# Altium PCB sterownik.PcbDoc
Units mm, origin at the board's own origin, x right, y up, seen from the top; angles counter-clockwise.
Board outline 218.44 x 160.02 mm, 2 copper layers (Top Layer, Bottom Layer); 44 components, 46 nets, 196 pads, 52 vias.
Unrouted connection lines stored in the file: 1.
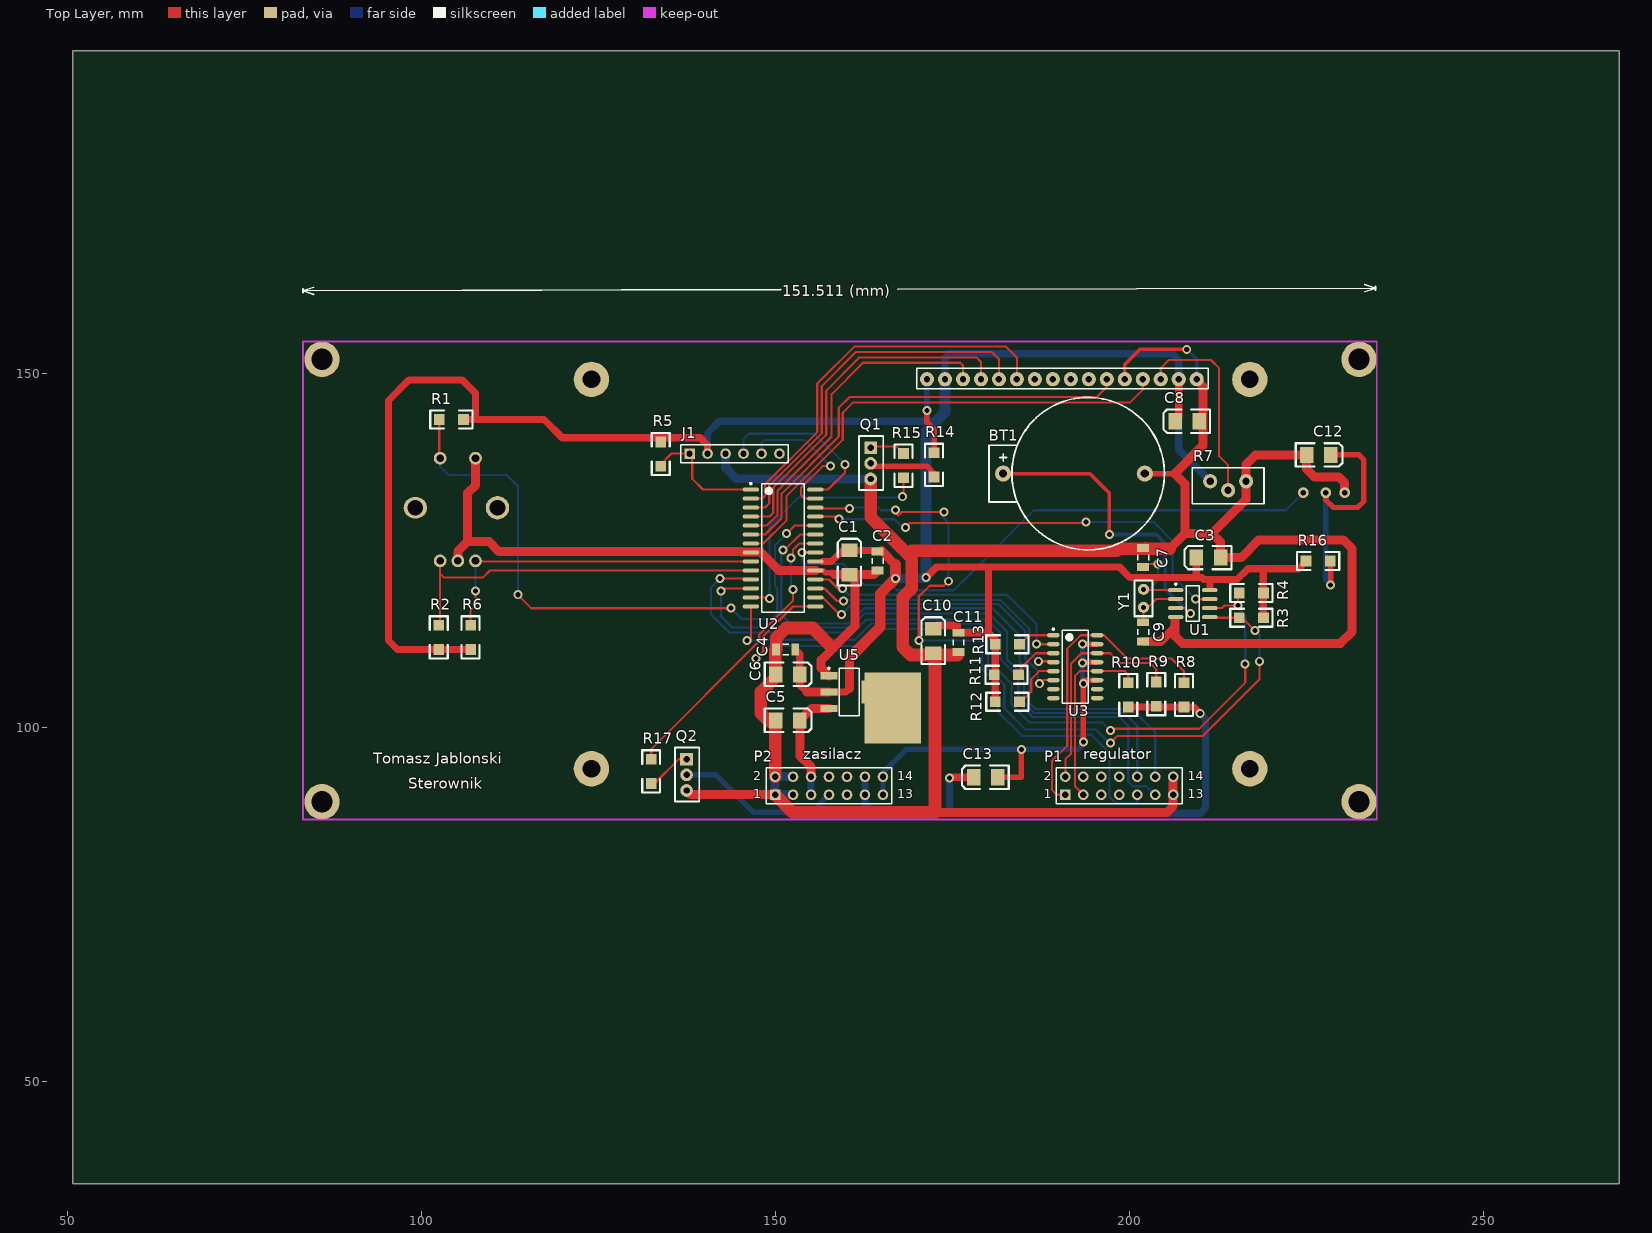
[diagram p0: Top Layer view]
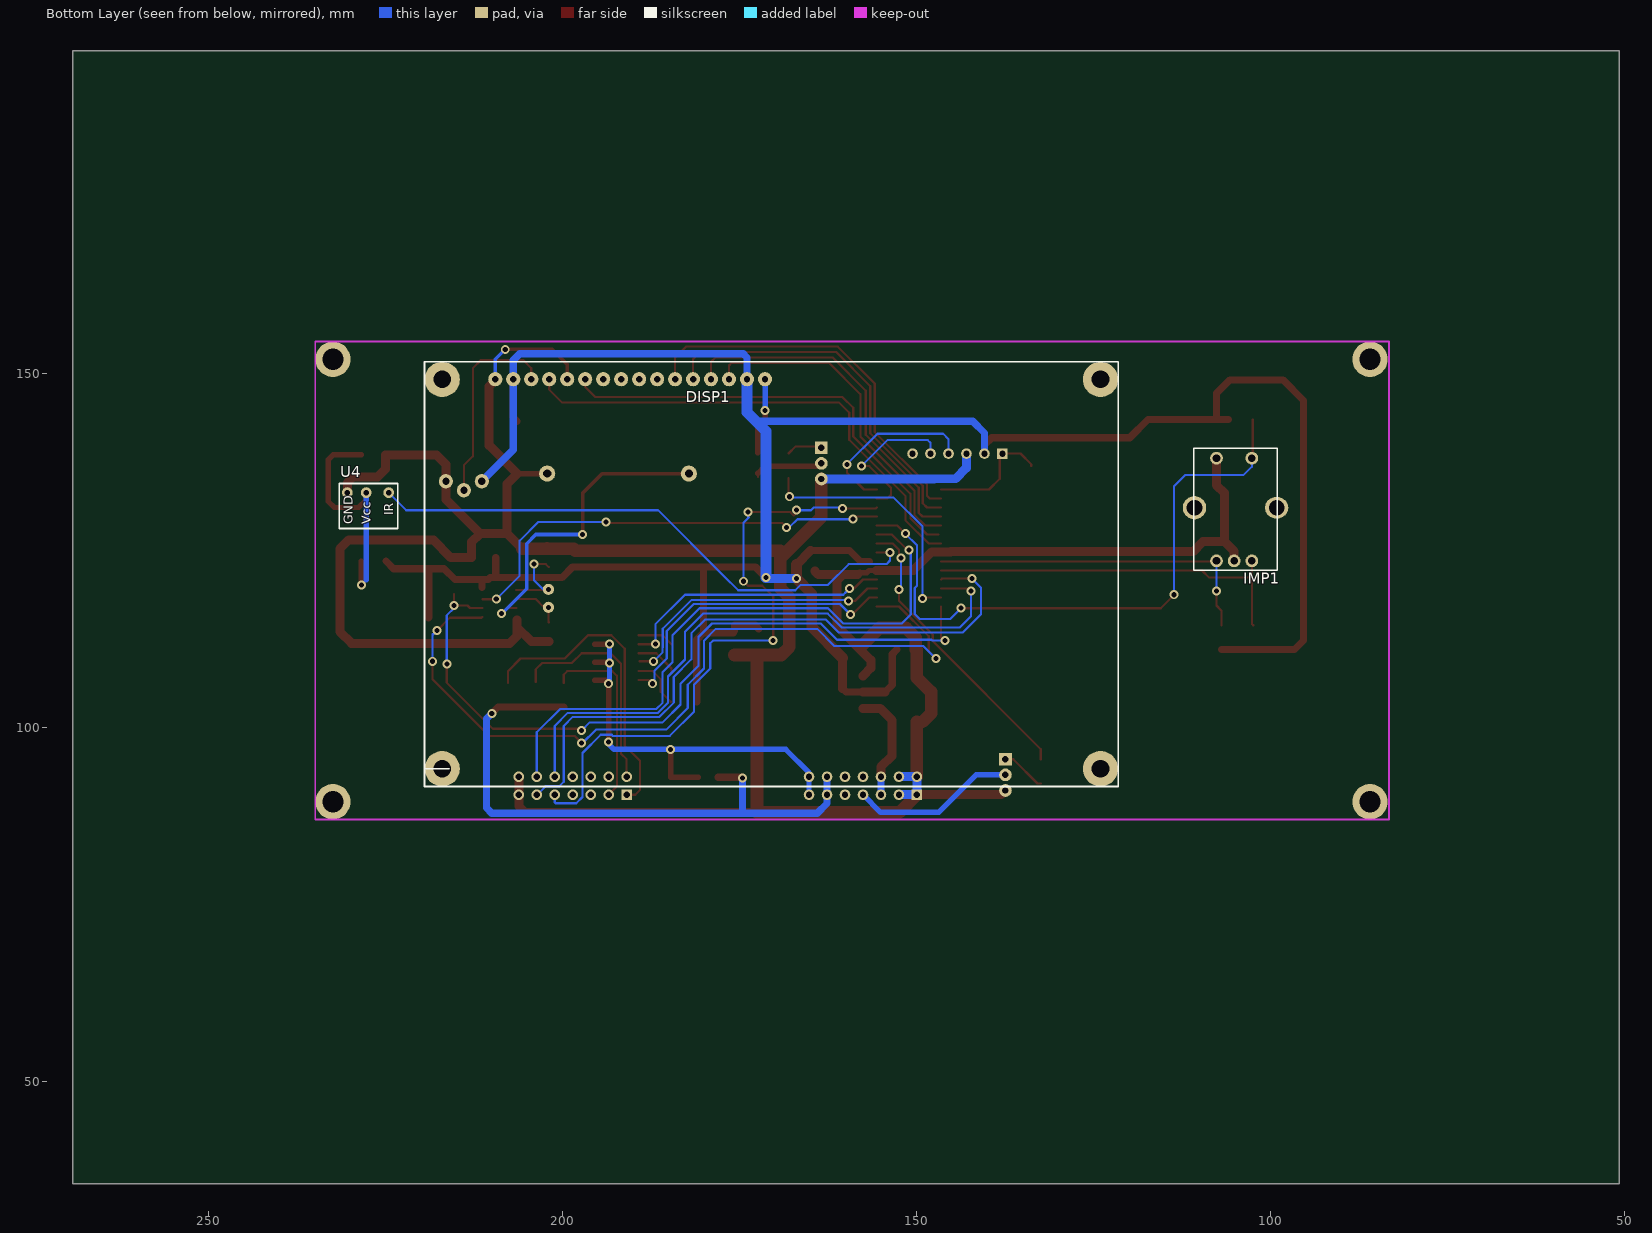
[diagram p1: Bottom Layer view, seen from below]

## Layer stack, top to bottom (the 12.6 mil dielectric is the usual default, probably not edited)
Top Solder: solder mask 0.0102, Solder Resist, Dk 3.5
Top Layer: signal copper 0.0356
Dielectric 1: dielectric 0.32, FR-4, Dk 4.8
Bottom Layer: signal copper 0.0356
Bottom Solder: solder mask 0.0102, Solder Resist, Dk 3.5

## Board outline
50.8,35.56 50.8,195.58 269.24,195.58 269.24,35.56

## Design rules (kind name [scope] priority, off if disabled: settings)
Clearance [All] p1: gap=0.254
PolygonConnect [All] p1: connectstyle=Relief reliefconductorwidth=0.254 reliefentries=4 polygonreliefangle="90 Angle" airgapwidth=0.254
RoomDefinition sterownik [InComponentClass('sterownik')] p1: confinementstyle=ConfineIn formatcopy=TRUE lockcomponents=FALSE outline 0,0 50.8,0 50.8,25.4 0,25.4
RoutingVias [All] p1: holewidth=0.711 width=1.27 viastyle="Through Hole" minholewidth=0.711 minwidth=1.27 maxholewidth=0.711 maxwidth=1.27
SolderMaskExpansion [All] p1: expansion=0.102
Width GNDI [InNet('GNDI')] p1: maxlimit=0.762 minlimit=0.762 preferedwidth=0.762
Width +VDD [InNet('+VDD')] p2: maxlimit=1.016 minlimit=1.016 preferedwidth=1.016
Width +5VI [InNet('+5VI')] p3: maxlimit=1.016 minlimit=1.016 preferedwidth=1.016
Width GND [InNet('GND')] p4: maxlimit=1.27 minlimit=1.27 preferedwidth=1.27
Width +5V [InNet('+5V')] p5: maxlimit=1.27 minlimit=1.016 preferedwidth=1.27
Width [All] p6: maxlimit=0.305 minlimit=0.305 preferedwidth=0.305
30 further rules are at their usual default settings.

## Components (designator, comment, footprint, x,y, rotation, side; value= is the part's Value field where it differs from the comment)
BT1 "Battery" BAT 194,135.5 r180 top
C1 "" 3528 160.5,125 r90 top
C2 "Cap" C1206 164.5,123.5 r270 top
C3 "" 3528 209.5,124 r180 top
C4 "Cap" C1206 151.5,111 r0 top
C5 "ELECTRO2" 3528 153.5,101 r0 top
C6 "ELECTRO2" 3528 153.5,107.5 r0 top
C7 "Cap" C1206 202,124 r90 top
C8 "" 3528 206.502,143.256 r180 top
C9 "Cap" C1206 202,113.5 r270 top
C10 "" 3528 172.339,113.919 r90 top
C11 "Cap" C1206 175.895,112.014 r270 top
C12 "" 3528 228.5,138.5 r0 top
C13 "" 3528 178.054,92.964 r180 top
DISP1 "LCD" LCD4x20 170.561,121.666 r180 bottom locked
IMP1 "IMP_PIHER" IMP_PIHER 105.492,130.732 r180 bottom
J1 "ICSP" HDR1X6 137.922,138.684 r0 top
P1 "regulator" HDR2X7 191,90.5 r0 top
P2 "zasilacz" HDR2X7 150,90.5 r0 top
Q1 "" BD139 163.5,139.5 r0 top
Q2 "BD139" BD139 137.5,95.5 r0 top
R1 "" 1206 106,143.5 r180 top
R2 "" 1206 102.5,111 r90 top
R3 "" 1206 219,115.5 r180 top
R4 "" 1206 219,119 r180 top
R5 "" 1206 133.858,136.906 r90 top
R6 "" 1206 107,111 r90 top
R7 "RPot" PR 214,133.5 r0 top
R8 "" 1206 207.772,102.87 r90 top
R9 "" 1206 203.835,102.997 r90 top
R10 "" 1206 199.898,102.87 r90 top
R11 "" 1206 181.102,103.632 r0 top
R12 "" 1206 180.975,107.442 r0 top
R13 "" 1206 181.102,111.76 r0 top
R14 "" 1206 172.466,138.811 r270 top
R15 "" 1206 168.148,135.255 r90 top
R16 "" 1206 225,123.5 r0 top
R17 "" 1206 132.5,95.5 r270 top
U1 "DS1307Z" SOIC8N_N 209,117.5 r0 top
U2 "PIC16F1936-I/SO" SOIC-SO28_N 151.13,125.349 r0 top
U3 "TLP281-4" TLP281-4 192.405,108.585 r0 top
U4 "IR" IR 228,131 r180 bottom
U5 "SPX1117" SOT223_N 160.5,105 r0 top
Y1 "XTAL" RAD0.1 202.057,116.967 r90 top

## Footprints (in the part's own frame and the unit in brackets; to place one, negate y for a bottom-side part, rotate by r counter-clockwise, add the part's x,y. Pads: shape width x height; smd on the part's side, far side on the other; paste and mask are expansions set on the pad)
1206 [mil]
  rect 60x60 smd: 1(0,0) 2(135,0)
  silkscreen extent -50,-50 185,50
3528 [mil]
  rect 75x90 smd: 1(0,0) 2(-135,0)
  silkscreen extent -195,-65 65,65
BAT [mil]
  round 90 hole 45: 1(463.58,-13.78) 2(-323.82,-13.78)
  silkscreen extent -433,-438 542,410
BD139 [mm]
  rect 1.8x1.8 hole 0.9: 1(0,0)
  round 1.8 hole 0.9: 2(0,-2.2) 3(0,-4.4)
  silkscreen extent -1.65,-5.97 1.78,1.65
C1206 [mm] "Chip Capacitor, Body 3.2x1.6mm, IPC High Density"
  rect 1.1x1.7 smd: 1(-1.35,0) 2(1.35,0)
  silkscreen extent -0.4,-0.75 0.4,0.75, body extent -1.7,-0.9 1.7,0.9, height 1.3
HDR1X6 [mm] "Connector; Header; 6 Position"
  rect 1.5x1.5 hole 0.9: 1(0,0)
  round 1.5 hole 0.9: 2(2.54,0) 3(5.08,0) 4(7.62,0) 5(10.16,0) 6(12.7,0)
  silkscreen extent -1.27,-1.27 13.97,1.27
HDR2X7 [mm] "Connector; Header; 7x2 Position"
  rect 1.5x1.5 hole 0.9: 1(0,0)
  round 1.5 hole 0.9: 2(0,2.54) 3(2.54,0) 4(2.54,2.54) 5(5.08,0) 6(5.08,2.54) 7(7.62,0) 8(7.62,2.54) 9(10.16,0) 10(10.16,2.54) 11(12.7,0) 12(12.7,2.54) 13(15.24,0) 14(15.24,2.54)
  silkscreen extent -1.27,-1.27 16.51,3.81
IMP_PIHER [mm]
  round 1.8 hole 1.1: 1(-2.2,-7.2) 2(0.3,-7.2) 3(2.8,-7.2) 4(-2.2,7.3) 5(2.8,7.3)
  round 3.3 hole 2.2: 71(-5.3,0.3)
  oval 3.3x3 hole 2.2: 72(6.3,0.3)
  silkscreen extent -5.4,-8.5 6.4,8.7
IR [mil]
  round 60 hole 30: 1(-96.73,85.43) 2(8.27,85.43) 3(133.27,85.43)
  silkscreen extent -142,-115 183,135
LCD4x20 [mm]
  round 5 hole 2.5: 0(-46.5,-27.5) 0(-46.5,27.5) 0(46.5,-27.5) 0(46.5,27.5)
  round 2 hole 0.9: 1(-39,27.525) 2(-36.46,27.525) 3(-33.92,27.525) 4(-31.38,27.525) 5(-28.84,27.525) 6(-26.3,27.525) 7(-23.76,27.525) 8(-21.22,27.525) 9(-18.68,27.525) 10(-16.14,27.525) 11(-13.6,27.525) 12(-11.06,27.525) 13(-8.52,27.525) 14(-5.98,27.525) 15(-3.44,27.525) 16(-0.9,27.525)
  silkscreen extent -49,-30 49,30
PR [mil]
  round 79 hole 40: 1(-100,50) 2(100,50) 3(0,0)
  silkscreen extent -200,-75 200,125
RAD0.1 [mil]
  round 62 hole 28: 1(0,0) 2(100,0)
  silkscreen extent -50,-50 150,50
SOIC8N_N [mm] "SOIC, 8-Leads, Body 4.9x3.9mm, Pitch 1.27mm, IPC Medium Density"
  oval 2.2x0.6 smd: 1(-2.4,1.905) 2(-2.4,0.635) 3(-2.4,-0.635) 4(-2.4,-1.905) 5(2.4,-1.905) 6(2.4,-0.635) 7(2.4,0.635) 8(2.4,1.905)
  silkscreen extent -2.52,-2.5 0.9,2.88, body extent -2,-2.5 2,2.5, height 1.75
SOIC-SO28_N [mm] "SOIC, 28-Leads, Body 17.9x7.5mm, Pitch 1.27mm, IPC Medium Density"
  oval 2.3x0.6 smd: 1(-4.55,8.255) 2(-4.55,6.985) 3(-4.55,5.715) 4(-4.55,4.445) 5(-4.55,3.175) 6(-4.55,1.905) 7(-4.55,0.635) 8(-4.55,-0.635) 9(-4.55,-1.905) 10(-4.55,-3.175) 11(-4.55,-4.445) 12(-4.55,-5.715) 13(-4.55,-6.985) 14(-4.55,-8.255) 15(4.55,-8.255) 16(4.55,-6.985) 17(4.55,-5.715) 18(4.55,-4.445) 19(4.55,-3.175) 20(4.55,-1.905) 21(4.55,-0.635) 22(4.55,0.635) 23(4.55,1.905) 24(4.55,3.175) 25(4.55,4.445) 26(4.55,5.715) 27(4.55,6.985) 28(4.55,8.255)
  silkscreen extent -4.67,-9.05 3,9.23, body extent -3.8,-9.05 3.8,9.05, height 2.65
SOT223_N [mm] "SOT223, 4-Leads, Body 6.5x3.5mm, Pitch 2.3mm, Lead Span 7mm, IPC Medium Density"
  rect 2.4x1 smd: 1(-2.9,2.3) 2(-2.9,0) 3(-2.9,-2.3)
  rect 2.4x3.3 smd: 4(2.9,0)
  silkscreen extent -3.02,-3.35 1.4,3.47, body extent -1.85,-3.35 1.85,3.35, height 1.7
TLP281-4 [mm]
  oval 1.75x0.6 smd: 1(-3.1,4.445) 2(-3.1,3.175) 3(-3.1,1.905) 4(-3.1,0.635) 5(-3.1,-0.635) 6(-3.1,-1.905) 7(-3.1,-3.175) 8(-3.1,-4.445) 9(3.1,-4.445) 10(3.1,-3.175) 11(3.1,-1.905) 12(3.1,-0.635) 13(3.1,0.635) 14(3.1,1.905) 15(3.1,3.175) 16(3.1,4.445)
  silkscreen extent -3.22,-5.15 1.83,5.42, body extent -2.2,-5.15 2.2,5.15, height 2

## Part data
BT1: "Multicell Battery"
C1 C3 C8 C10 C12 C13: library part ELECTRO2, "Electrolytic Capacitor"
C2 C4 C7 C9 C11: "Capacitor"
C5 C6: "Electrolytic Capacitor"
J1: library part "Header 6", "Header, 6-Pin"
P1 P2: library part "Header 7X2", "Header, 7-Pin, Dual row"
Q1 Q2: library part NPN1, "NPN Transistor"
R1 R2 R3 R4 R5 R6 R8 R9 R10 R11 R12 R13 R14 R15 R16 R17: library part Res2, "Resistor"
R7: "Potentiometer"
U1: "64 X 8 Serial Real-Time Clock"
U2: "CMOS Microcontroller with LCD Driver, 8K (words) Program Memory, 256 Bytes Data Memory, 512 Bytes SRAM, 25 I/O's, 1.8V-5.5V, 28-Pin SOIC, Industrial Temperature"
Y1: "Crystal Oscillator"

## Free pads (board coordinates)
  round 5 hole 3: 0(86,89.5) 0(86,152) 0(232.5,89.5) 0(232.5,152)
  rect 8x10 smd: 0(166.624,102.743)

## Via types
v1: diameter 1.27, hole 0.711, Top Layer to Bottom Layer, 52 vias

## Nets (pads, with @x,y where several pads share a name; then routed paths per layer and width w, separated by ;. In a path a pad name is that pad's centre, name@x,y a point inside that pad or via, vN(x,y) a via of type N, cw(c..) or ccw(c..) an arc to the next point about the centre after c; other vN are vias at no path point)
+5V: C1.1 C2.1 C3.1 C4.2 C6.1 C8.1 C10.1 C11.1 DISP1.2 DISP1.15 J1.2 pad.0@166.624,102.743 R1.1 R2.1 R3.1 R4.1 R5.2 R6.1 R7.1 R11.1 R12.1 R13.1 R16.1 U1.8 U2.20 U5.2 | length 372
  Top Layer w1.016: R1.1 117.358,143.5 119.937,140.921 139.446,140.921 140.462,139.905 J1.2 ; R6.1 R2.1 96.649,111 95.377,112.272 95.377,146.177 98.298,149.098 105.791,149.098 107.696,147.193 107.696,143.627 ; C4.2 153.5,110.35 C6.1 153.5,106 154.5,105 ; U2.20@156.718,123.444 157.988,123.444 159.544,125 C1.1 C2.1@165,125 ; U5.2 160,105 160.5,105.5 ; v1(171.323,121.158) 172.847,122.682 180.213,122.682 ; C10.1 172.847,114.427 175.768,114.427 C11.1@175.768,113.665 ; C11.1 180.133,113.364 ; R11.1 R13.1 181.102,112.395 180.133,113.364 ; C8.1 207.021,143.775 DISP1.2 ; 209.5,121.412 C3.1 ; 211.455,119.761 211.455,120.904 ; R3.1 218.948,115.552 218.948,122.428 ; R16.1 223.928,122.428 218.948,122.428 ; 180.133,113.364 180.133,122.602 180.213,122.682 ; 180.213,122.682 198.628,122.682 200.152,121.158 210.312,121.158 210.566,120.904 211.455,120.904 ; 211.455,120.904 215.265,120.904 216.789,122.428 218.948,122.428
  Top Layer w1.27: 154.5,105 U5.2 ; 160.5,105.5 160.5,109.827 ; C2.1@165,125 167,123
  Top Layer w1.524: 160.5,109.827 164.846,114.173 164.846,118.877 v1(167,121.031) 167,123
  Bottom Layer w1.016: J1.2 140.462,141.605 142.113,143.256 172.662,143.256 ; DISP1.15 174.001,152.262 174.52,152.781 206.121,152.781 207.021,151.881 DISP1.2 207.021,139.209 R7.1
  Bottom Layer w1.27: v1(167,121.031) 171.196,121.031 v1(171.323,121.158)
  Bottom Layer w1.524: v1(171.323,121.158) 171.323,141.848 174.001,144.526 DISP1.15
+5VI: C13.1 P2.11 P2.12 R8.1 R9.1 R10.1 | length 85.5
  Top Layer w1.016: v1(174.625,92.837) 174.752,92.964 C13.1 ; R10.1 R8.1 209.169,102.87 v1(210.058,101.981)
  Bottom Layer w1.016: P2.12 P2.11 162.7,89.268 164.079,87.889 174.371,87.889 ; v1(174.625,92.837) 174.625,88.143 174.371,87.889 ; v1(210.058,101.981) 210.82,101.219 210.82,88.646 210.063,87.889 174.371,87.889
+VDD: C5.1 P2.5 P2.6 U5.3 | length 16
  Top Layer w1.27: P2.6 155.08,94.42 153.5,96 C5.1 155.2,102.7 U5.3
  Bottom Layer w1.016: P2.5 P2.6
A: IMP1.1 R6.2 U2.9 | length 48.3
  Top Layer w0.305: R6.2 107,116.525 107.696,117.221 v1(107.696,119.253) ; IMP1.1 107.78,123.444 U2.9
  Bottom Layer w0.305: IMP1.1 107.692,119.257 v1(107.696,119.253)
B: IMP1.3 R2.2 U2.10 | length 53.7
  Top Layer w0.305: R2.2 102.692,114.621 102.692,121.717 ; IMP1.3 102.692,121.717 ; U2.10 109.728,122.174 108.712,121.158 103.251,121.158 102.692,121.717
BAT: BT1.1 U1.3 | length 44.2
  Top Layer w0.305: U1.3 207.874,116.865 v1(208.661,116.078)
  Top Layer w0.508: BT1.1 194.477,135.85 197.231,133.096 v1(197.231,127.254)
  Bottom Layer w0.508: v1(197.231,127.254) 203.835,127.254 205.13,125.959 205.13,119.609 v1(208.661,116.078)
BLIGHT: R15.1 U2.13 | length 36.1
  Top Layer w0.305: U2.13 v1@149.225,118.364 ; v1(168.021,132.588) 168.148,132.715 R15.1
  Bottom Layer w0.305: v1(149.225,118.237) 149.225,128.397 153.289,132.461 167.894,132.461 v1(168.021,132.588)
CS: U2.16 U3.6 | length 43.3
  Top Layer w0.305: U2.16 156.718,118.364 159.131,115.951 v1(159.385,115.951) ; v1(187.325,106.172) 187.833,106.68 U3.6
  Bottom Layer w0.305: v1(159.385,115.951) 160.858,117.424 181.534,117.424 185.344,113.614 185.344,109.728 187.071,108.001 187.071,106.426 v1(187.325,106.172)
CSI: P1.3 R10.2 U3.12 | length 26.4
  Top Layer w0.305: P1.3 192.384,91.656 192.384,107.294 193.04,107.95 U3.12 199.39,107.95 199.898,107.442 R10.2
D0: DISP1.11 U2.2 | length 55.2
  Top Layer w0.305: U2.2 148.209,132.334 148.59,132.715 148.59,134.344 155.956,141.71 155.956,148.59 161.163,153.797 182.626,153.797 184.161,152.262 DISP1.11
D1: DISP1.12 U2.3 | length 52.7
  Top Layer w0.305: U2.3 148.59,131.064 149.174,131.648 149.174,134.138 156.591,141.555 156.591,148.209 161.417,153.035 180.594,153.035 181.621,152.008 DISP1.12
D2: DISP1.13 U2.4 | length 50.2
  Top Layer w0.305: U2.4 149.225,129.794 149.733,130.302 149.733,133.858 157.226,141.351 157.226,147.574 161.925,152.273 178.435,152.273 179.081,151.627 DISP1.13
D3: DISP1.14 U2.5 | length 47.1
  Top Layer w0.305: U2.5 148.844,128.524 150.368,130.048 150.368,133.477 157.988,141.097 157.988,147.066 162.433,151.511 176.149,151.511 176.541,151.119 DISP1.14
E: DISP1.6 U2.6 | length 64
  Top Layer w0.305: U2.6@146.939,127.254 148.59,127.254 150.927,129.591 150.927,133.02 159.004,141.097 159.004,145.161 160.528,146.685 195.453,146.685 196.861,148.093 DISP1.6
GND: BT1.2 C1.2 C2.2 C3.2 C4.1 C5.2 C6.2 C7.2 C8.2 C9.2 C10.2 C11.2 C12.2 DISP1.1 DISP1.5 IMP1.2 IMP1.4 J1.3 P1.13 P1.14 P2.1 P2.2 P2.3 P2.4 Q1.3 Q2.3 R7.2 U1.4 U2.8 U2.19 U4.1 U5.1 | length 475.5
  Top Layer w0.508: DISP1.5 199.401,151.268 201.549,153.416 v1(208.153,153.416)
  Top Layer w0.762: U2.19@155.956,122.174 156.753,122.174 157.07,121.856 158.017,121.856 158.08,121.92 158.429,121.571 ; BT1.2 206.462,135.85
  Top Layer w1.27: IMP1.2 105.192,124.877 106.553,126.238 ; IMP1.4 107.692,134.235 106.553,133.096 106.553,126.238 ; Q2.3 138.1,90.5 P2.1 ; C5.2@149.222,100.778 C5.2@150,100.778 ; U2.19 150.495,122.174 147.874,124.795 145.238,124.795 145.192,124.841 110.998,124.841 109.601,126.238 106.553,126.238 ; U5.1 156.5,108.4 156.5,109.51 161.29,114.3 161.29,120.781 C1.2 ; 158.429,121.571 C1.2 ; C2.2@164.425,122.075 163.921,121.571 C1.2 ; C10.2 C10.2@172.593,110.236 ; 172.593,88.016 205.364,88.016 206.24,88.892 P1.13 P1.14 ; C9.2 204.479,112.15 206.502,114.173 ; C7.2 C7.2@202.225,125.575 ; 205.74,125.222 207.899,127.381 ; 206.502,115.189 206.502,114.173 ; DISP1.1@209.942,148.683 210.439,148.186 210.439,139.827 206.462,135.85 207.899,134.413 207.899,127.381 ; U4.1 230.457,134.541 229.616,135.382 226.187,135.382 225.071,136.498 C12.2 217.875,138.5 216.54,137.165 R7.2 216.54,132.212 211.709,127.381 ; 206.502,114.173 206.502,112.903 207.518,111.887 229.87,111.887 231.521,113.538 231.521,125.222 230.251,126.492 218.313,126.492 215.821,124 C3.2 212.929,126.161 211.709,127.381 ; 207.899,127.381 211.709,127.381
  Top Layer w1.778: C5.2@149.222,100.778 148,102 148,105 150,107 C4.1@150,111 ; P2.1 152.484,88.016 172.593,88.016 C10.2@172.593,110.236 ; P2.2 C5.2@150,100.778 ; C4.1 150.15,112.65 151.546,114.046 155.321,114.046 157.988,111.379 ; Q1.3 163.5,129.743 169.291,123.952 ; C11.2@175.768,110.236 C10.2@172.593,110.236 ; 205.74,125.222 198.501,125.222 198.247,124.968 169.291,124.968 169.291,119.634 168.021,118.364 168.021,111.379 169.164,110.236 C10.2@172.593,110.236
  Bottom Layer w0.508: v1(208.153,153.416) 209.561,152.008 DISP1.1
  Bottom Layer w1.27: J1.3 143.002,136.652 144.526,135.128 147.574,135.128 147.602,135.1 Q1.3 ; P2.3 P2.1 P2.2 P2.4
GNDI: C13.2 P2.13 P2.14 U3.11 U3.13 U3.15 | length 61.9
  Top Layer w0.762: C13.2@180.848,92.964 184.785,92.964 v1(184.785,96.901) ; v1(193.421,109.093) 193.421,109.22 U3.13 ; v1(193.421,111.76) U3.15 ; v1@193.548,97.663 v1(193.548,106.172) 193.548,106.426 193.675,106.553 193.548,106.68 U3.11
  Bottom Layer w0.762: P2.13 P2.14 165.24,93.612 168.529,96.901 v1(184.785,96.901) 192.786,96.901 v1@193.548,97.663 ; v1(193.421,109.093) 193.421,106.299 v1(193.548,106.172) ; v1@193.421,109.22 v1(193.421,111.76)
  other v1: 193.548,97.917
IR: U2.21 U4.3 | length 81.3
  Top Layer w0.305: v1(153.797,124.714) U2.21
  Bottom Layer w0.305: v1(153.797,124.714) 153.797,123.571 154.305,123.063 159.639,123.063 162.56,120.142 166.416,120.142 167.178,119.38 175.26,119.38 177.33,121.45 186.563,130.683 222.128,130.683 U4.3
ISPCLK: J1.5 U2.27 | length 21.7
  Top Layer w0.305: U2.27 154.178,132.334 153.67,132.842 153.67,133.858 156.718,136.906 v1(157.861,136.906)
  Bottom Layer w0.305: J1.5 148.082,140.208 148.463,140.589 154.178,140.589 v1(157.861,136.906)
ISPDAT: J1.4 U2.28 | length 24.8
  Top Layer w0.305: U2.28 157.48,133.604 159.893,136.017 v1(159.893,137.16)
  Bottom Layer w0.305: J1.4 145.542,140.716 146.304,141.478 155.575,141.478 v1(159.893,137.16)
K: DISP1.3 R7.3 | length 28.5
  Top Layer w0.305: DISP1.3 204.481,150.76 205.613,151.892 211.582,151.892 212.725,150.749 212.725,138.303 214,137.028 R7.3
MCLR: J1.1 R5.1 U2.1 | length 17.6
  Top Layer w0.305: R5.1 133.858,137.16 135.382,138.684 J1.1 138.303,138.303 138.303,135.128 139.827,133.604 U2.1
MUTE: P1.12 U2.23 | length 87.2
  Top Layer w0.305: v1(151.13,125.095) 151.384,125.095 153.543,127.254 U2.23
  Bottom Layer w0.305: v1(151.13,125.095) 150.876,124.841 150.876,115.951 152.146,114.681 160.401,114.681 162.56,116.84 180.721,116.84 184.531,113.03 184.531,109.22 185.928,107.823 185.928,103.505 186.817,102.616 200.406,102.616 203.7,99.322 P1.12
NetC7_1: C7.1 U1.1 Y1.2 | length 11.7
  Top Layer w0.305: C7.1 202.413,123.063 v1(204.089,123.063) ; Y1.2 202.159,119.405 U1.1
  Bottom Layer w0.305: Y1.2 202.819,119.507 204.089,120.777 v1(204.089,123.063)
NetC9_1: C9.1 U1.2 Y1.1 | length 7.2
  Top Layer w0.305: C9.1 202.057,114.907 Y1.1 202.692,116.967 203.86,118.135 U1.2
NetC12_1: C12.1 R16.2 U4.2 | length 34.7
  Top Layer w0.305: R16.2 R16.2@228.473,123.456
  Top Layer w0.762: U4.2 227.79,132.128 228.854,131.064 232.283,131.064 233.172,131.953 233.172,137.795 232.467,138.5 C12.1 ; v1(228.473,120.142) R16.2@228.473,123.456
  Bottom Layer w0.305: 227.79,120.825 v1(228.473,120.142)
  Bottom Layer w0.762: 227.79,120.825 U4.2
NetDISP1_16: DISP1.16 R14.1 | length 10.8
  Top Layer w0.762: v1(171.45,144.78) 171.45,143.129 172.466,142.113 R14.1
  Bottom Layer w0.762: v1(171.45,144.78) DISP1.16@171.45,149.18
NetQ1_1: Q1.1 R15.2 | length 5.2
  Top Layer w0.305: Q1.1 163.7,139.7 167.132,139.7 R15.2
NetQ1_2: Q1.2 R14.2 | length 10.1
  Top Layer w0.305: Q1.2 Q1.2@163.894,136.906 ; R14.2 R14.2@172.466,135.89
  Top Layer w0.762: Q1.2@163.894,136.906 171.45,136.906 R14.2@172.466,135.89
NetQ2_1: Q2.1 R17.2 | length 6.4
  Top Layer w0.305: R17.2 132.965,92.071 136.394,95.5 Q2.1
NetR11_2: R11.2 U3.5 | length 7.4
  Top Layer w0.305: R11.2@184.785,103.632 186.182,105.029 186.182,106.807 187.325,107.95 U3.5
NetR12_2: R12.2 U3.3 | length 6.2
  Top Layer w0.305: R12.2@184.658,107.696 184.658,108.331 186.817,110.49 U3.3
NetR13_2: R13.2 U3.1 | length 5.2
  Top Layer w0.305: R13.2@184.658,111.76 185.928,113.03 U3.1
RS: DISP1.4 U2.7 | length 70.1
  Top Layer w0.305: U2.7 148.336,125.984 151.638,129.286 151.638,132.715 159.563,140.64 159.563,144.45 161.036,145.923 200.152,145.923 201.941,147.712 DISP1.4
RTC: U1.7 U2.25 | length 64.1
  Top Layer w0.305: U2.25 158.623,129.794 v1(159.004,129.413) ; v1(168.402,128.27) 169.012,128.88 193.777,128.88 v1(193.929,129.032) ; v1(209.423,118.11) U1.7@211.375,118.11
  Bottom Layer w0.305: v1(159.004,129.413) 166.878,129.413 168.021,128.27 v1(168.402,128.27) ; v1(193.929,129.032) 203.454,129.032 206.121,126.365 206.121,121.412 v1(209.423,118.11)
SCK: U2.17 U3.4 | length 39.9
  Top Layer w0.305: U2.17 156.972,119.634 158.75,117.856 v1(159.639,117.856) ; v1(187.198,109.347) U3.4@189.178,109.347
  Bottom Layer w0.305: v1@159.639,117.602 160.02,117.983 181.864,117.983 185.903,113.944 185.903,111.303 185.928,111.278 185.928,110.617 v1(187.198,109.347)
SCKI: P1.2 R9.2 U3.14 | length 31.7
  Top Layer w0.305: P1.2 191.008,93.048 191.008,95.504 191.825,96.321 191.825,109.021 193.294,110.49 U3.14 197.358,110.49 198.755,109.093 202.946,109.093 203.835,108.204 R9.2
SCL: R4.2 U1.6 U2.14 | length 107.6
  Top Layer w0.305: v1(146.05,112.268) 146.431,112.268 146.58,112.119 U2.14 ; v1(197.358,99.568) 197.612,99.822 209.903,99.822 216.408,106.327 v1(216.408,108.966) ; U1.6 213.131,116.865 213.487,117.221 v1(215.392,117.221) R4.2@215.392,118.821
  Bottom Layer w0.305: v1@146.05,111.76 v1(146.05,112.268) 147.828,112.268 147.955,112.395 161.29,112.395 163.576,114.681 178.943,114.681 180.848,112.776 180.848,108.712 183.388,106.172 183.388,103.251 185.928,100.711 196.215,100.711 v1(197.358,99.568) ; v1(215.392,117.221) 215.392,116.84 216.408,115.824 v1(216.408,108.966)
SDA: R3.2 U1.5 U2.15 | length 114.6
  Top Layer w0.305: v1(147.32,109.728) 148.336,110.744 148.336,112.903 152.527,117.094 U2.15 ; v1(197.358,97.79) 198.374,98.806 210.439,98.806 218.44,106.807 v1(218.44,109.347) ; U1.5 211.495,115.5 R3.2 215.97,115.5 v1(217.805,113.665)
  Bottom Layer w0.305: v1(147.32,109.728) 149.098,111.506 161.671,111.506 164.084,113.919 178.435,113.919 180.086,112.268 180.086,108.331 182.372,106.045 182.372,102.743 185.42,99.695 195.326,99.695 197.231,97.79 v1(197.358,97.79) ; v1(217.805,113.665) 218.313,113.157 218.44,113.157 v1(218.44,109.347)
SDO: U2.18 U3.2 | length 38.3
  Top Layer w0.305: U2.18 157.623,120.904 158.893,119.634 v1(159.512,119.634) ; v1(186.944,111.76) U3.2
  Bottom Layer w0.305: 160.02,119.126 160.401,118.745 182.753,118.745 186.944,114.554 v1(186.944,111.76)
SDOI: P1.1 R8.2 U3.16 | length 44.1
  Top Layer w0.305: P1.1 189.789,90.5 189.103,91.186 189.103,95.25 191.266,97.413 191.266,111.129 193.167,113.03 U3.16 196.469,113.03 199.771,109.728 205.994,109.728 207.772,107.95 R8.2
SEL1: P1.9 U2.26 | length 90.4
  Top Layer w0.305: U2.26 155.807,130.937 v1(160.528,130.937) ; v1(167.005,130.683) 167.005,130.302 167.386,129.921 167.894,130.429 v1(173.863,130.429) ; v1(170.307,112.268) 170.307,118.491 171.831,120.015 173.863,120.015 v1(174.498,120.65)
  Bottom Layer w0.305: v1(160.528,130.937) 160.655,131.064 164.592,131.064 164.973,130.683 v1(167.005,130.683) ; v1@170.18,112.268 v1(170.307,112.268) 178.816,112.268 179.197,111.887 179.197,108.331 181.483,106.045 181.483,102.235 184.912,98.806 192.964,98.806 193.117,98.958 194.666,98.958 197.231,96.393 197.231,93.53 197.236,93.524 197.236,90.165 198.12,89.281 201.041,89.281 201.16,89.4 P1.9 ; v1(173.863,130.429) 173.863,129.794 173.736,129.667 174.498,128.905 v1(174.498,120.65)
SEL2: P1.11 U2.11 | length 93.7
  Top Layer w0.305: v1(142.24,121.031) 146.453,121.031 U2.11
  Bottom Layer w0.305: v1(142.24,121.031) 140.97,119.761 140.97,115.951 143.51,113.411 161.036,113.411 162.865,115.24 179.908,115.24 181.864,113.284 181.864,109.615 184.347,107.131 184.347,103.505 186.354,101.498 198.603,101.498 199.898,100.203 199.898,92.329 200.533,91.694 202.438,91.694 203.632,90.5 P1.11
SEL3: P1.10 U2.12 | length 86.4
  Top Layer w0.305: v1(142.367,119.253) 142.748,119.634 U2.12
  Bottom Layer w0.305: v1(142.367,119.253) 142.367,115.697 143.942,114.122 160.632,114.122 162.588,116.078 180.213,116.078 182.753,113.538 182.753,109.601 185.152,107.202 185.152,103.491 186.586,102.057 199.314,102.057 201.16,100.211 P1.10
STDBY: R17.1 U2.22 | length 41.9
  Top Layer w0.305: R17.1 132.5,96.94 147.777,112.217 147.777,113.134 152.527,117.884 v1(152.527,119.507) ; v1@152.527,123.571 152.527,125.095 153.416,125.984 U2.22
  Bottom Layer w0.305: v1(152.273,123.952) 152.273,119.761 v1(152.527,119.507)
STDBYO: P2.7 Q2.2 | length 23.3
  Bottom Layer w0.762: Q2.2 141.65,93.3 146.939,88.011 155.131,88.011 P2.7
SW: IMP1.5 R1.2 U2.24 | length 89.2
  Top Layer w0.305: R1.2 102.571,138.153 IMP1.5 ; v1(113.665,118.745) 115.57,116.84 v1(143.764,116.84) ; v1(151.638,127.381) 152.781,128.524 U2.24
  Bottom Layer w0.305: IMP1.5 102.692,136.83 103.886,135.636 112.141,135.636 113.665,134.112 v1(113.665,118.745) ; v1(143.764,116.84) 145.288,115.316 149.606,115.316 150.317,116.027 150.317,119.685 149.987,120.015 149.987,125.73 v1(151.638,127.381)
pads on no net: DISP1.0 DISP1.7 DISP1.8 DISP1.9 DISP1.10 IMP1.71 IMP1.72 J1.6 P1.4 P1.5 P1.6 P1.7 P1.8 P2.8 P2.9 P2.10 U3.7 U3.8 U3.9 U3.10 U5.4

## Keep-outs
Keep-Out Layer:
  lines w0.254: 83.312,87 235,87 235,154.5 83.312,154.5 83.312,87

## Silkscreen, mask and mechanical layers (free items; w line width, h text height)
Top Overlay:
  lines w0.254: 83.311,161.925 83.313,161.417 ; 84.835,162.183 83.312,161.671 ; 84.837,161.167 83.312,161.671 ; 150.79,161.841 83.312,161.671 ; 167.345,161.882 234.823,162.052 ; 233.298,162.556 234.823,162.052 ; 233.3,161.54 234.823,162.052 ; 234.822,162.306 234.824,161.798 ; 170,147.828 211.201,147.828 211.201,150.749 170,150.749 170,147.828
  text "151.511 (mm)" at 151.046,160.927 h1.52 r0.14
  text "Tomasz Jablonski" at 93.218,94.869 h1.52
  text "Sterownik" at 98.171,91.313 h1.52
Mechanical 1:
  lines w0.254: 50.8,35.56 269.24,35.56 269.24,195.58 50.8,195.58 50.8,152.4 50.8,35.56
